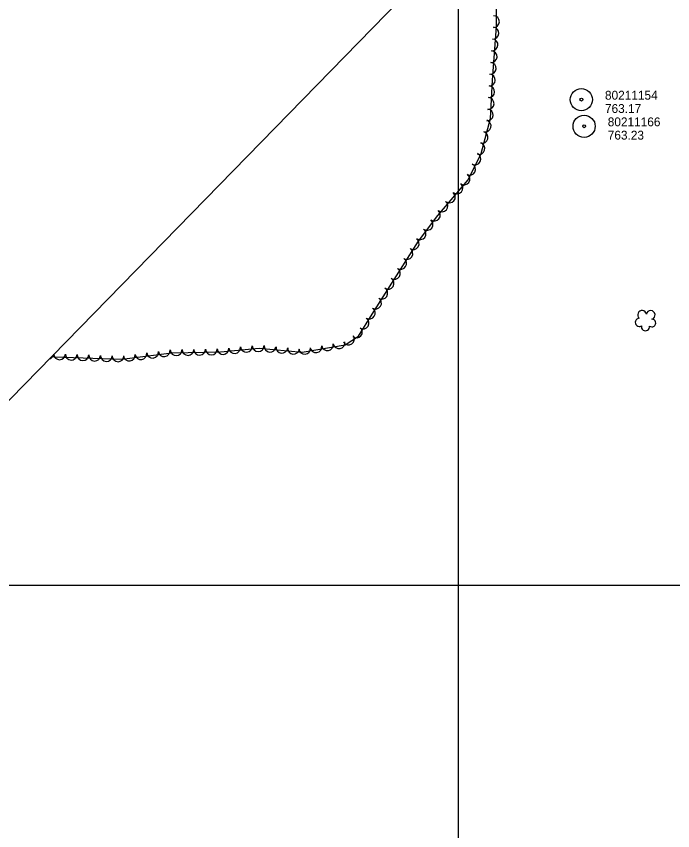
# Model space of a CAD drawing. Extents: x 591954 to 597000, y 198576 to 213500.
# Drawn here: x 593200 to 593645, y 205834 to 206385 of the extents above; entities that cross this region are included whole.
import ezdxf

# ---------------------------------------------------------------- set-up
doc = ezdxf.new("R2010")
doc.units = 0
for name, color, linetype in [('Level 10', 7, 'Continuous'), ('Level 18', 7, 'Continuous'), ('Level 4', 7, 'Continuous'), ('Level 6', 7, 'Continuous')]:
    doc.layers.add(name, color=color, linetype=linetype)

msp = doc.modelspace()

# ---------------------------------------------------------------- linework, layer by layer
at = {"layer": 'Level 10'}
for p, q in [((593500, 205500), (593500, 207000)), ((593500, 205500), (593500, 207000)), ((593500, 204500), (593500, 206500)), ((592000, 206000), (594000, 206000)), ((592500, 206000), (594000, 206000)), ((593000, 206000), (595500, 206000)), ((593500, 206000), (595500, 206000)), ((593500, 204500), (593500, 206000))]:
    msp.add_line(p, q, dxfattribs=at)
at = {"layer": 'Level 18'}
msp.add_lwpolyline([(593224.27, 206154.82), (593226.09, 206154.7), (593271.97, 206153.01), (593305.78, 206157.31), (593338.87, 206157.95), (593364.91, 206160.45), (593394.13, 206157.72), (593423.16, 206162.65), (593432.29, 206168.61), (593441.64, 206183.56), (593472.83, 206232.93), (593485.99, 206250.28), (593506.5, 206274.56), (593515.27, 206292.31), (593521.67, 206316.11), (593523.01, 206342.07), (593525.86, 206378.29), (593525.72, 206418.97), (593532.97, 206465.61), (593530.87, 206468.59)], dxfattribs=at)
for centre, radius, start, end in [((593523.75, 206381.59), 3.97, 269.813, 89.7976), ((593523.42, 206373.81), 3.97, 265.4895, 85.4742), ((593522.8, 206365.89), 3.97, 265.4973, 85.4819), ((593522.17, 206357.97), 3.97, 265.4895, 85.4742), ((593521.55, 206350.05), 3.97, 265.4967, 85.4814), ((593520.98, 206342.09), 3.97, 266.2991, 86.2838), ((593520.51, 206334.13), 3.97, 267.0722, 87.0568), ((593520.11, 206326.19), 3.97, 267.0722, 87.0568), ((593519.52, 206318.39), 3.96, 264.1336, 84.1182), ((593518.13, 206310.95), 3.97, 254.9536, 74.9383), ((593516.07, 206303.27), 3.97, 254.9536, 74.9383), ((593513.92, 206295.69), 3.96, 253.3555, 73.3402), ((593511.15, 206288.66), 3.97, 243.7102, 63.6949), ((593507.63, 206281.53), 3.97, 243.707, 63.6917), ((593503.76, 206275.03), 3.95, 234.6607, 54.6453), ((593499.01, 206268.92), 3.97, 229.8107, 49.7954), ((593493.88, 206262.85), 3.97, 229.8153, 49.8), ((593488.75, 206256.78), 3.97, 229.8107, 49.7954), ((593483.68, 206250.57), 3.97, 231.7804, 51.765), ((593478.8, 206244.25), 3.97, 232.8465, 52.8312), ((593474, 206237.92), 3.97, 232.8479, 52.8326), ((593469.36, 206231.27), 3.97, 237.2837, 57.2684), ((593465.08, 206224.56), 3.97, 237.7256, 57.7103), ((593460.84, 206217.84), 3.97, 237.7234, 57.708), ((593456.59, 206211.12), 3.97, 237.7195, 57.7042), ((593452.35, 206204.4), 3.97, 237.7234, 57.708), ((593448.1, 206197.69), 3.97, 237.7195, 57.7042), ((593443.86, 206190.97), 3.97, 237.7195, 57.7042), ((593439.62, 206184.24), 3.97, 237.8854, 57.87), ((593624.38, 206183.05), 2.97, 8.9237, 230.1575), ((593630.23, 206182.99), 2.97, 286.5745, 169.5477), ((593435.4, 206177.5), 3.97, 238.0015, 57.9862), ((593622.56, 206177.99), 2.78, 91.8946, 299.6675), ((593631.04, 206177.53), 2.61, 231.2797, 89.2123), ((593430.98, 206171.39), 3.89, 229.4966, 49.4813), ((593626.67, 206175.03), 2.78, 168.5716, 9.5826), ((593425.54, 206166.68), 3.97, 213.1418, 33.1265), ((593356.22, 206161.71), 3.97, 185.5023, 5.487), ((593364.3, 206162.15), 3.96, 180.8839, 0.8686), ((593372.43, 206161.84), 3.97, 174.6579, 354.6426), ((593380.35, 206161.1), 3.97, 174.6572, 354.6419), ((593403.45, 206161.41), 3.97, 189.6418, 9.6265), ((593411.28, 206162.74), 3.97, 189.649, 9.6336), ((593419.08, 206164.1), 3.96, 190.3028, 10.2875), ((593221.86, 206157.07), 3.97, 281.6047, 349.7176), ((593229.73, 206156.65), 3.97, 184.2163, 357.8), ((593237.67, 206156.35), 3.97, 177.902, 357.8867), ((593245.61, 206156.06), 3.97, 177.9018, 357.8865), ((593253.55, 206155.77), 3.97, 177.902, 357.8867), ((593277, 206155.75), 3.97, 187.2588, 7.2435), ((593284.88, 206156.75), 3.97, 187.2579, 7.2425), ((593292.77, 206157.75), 3.97, 187.2588, 7.2435), ((593300.65, 206158.76), 3.97, 187.2579, 7.2425), ((593308.76, 206159.4), 3.97, 181.826, 1.8106), ((593316.73, 206159.6), 3.97, 181.1108, 1.0954), ((593324.67, 206159.75), 3.97, 181.1035, 1.0882), ((593332.62, 206159.91), 3.97, 181.1109, 1.0956), ((593340.44, 206160.27), 3.97, 184.2675, 4.2522), ((593348.31, 206160.94), 3.97, 185.503, 5.4877), ((593388.26, 206160.36), 3.97, 174.6579, 354.6426), ((593395.75, 206160.36), 3.95, 185.6641, 5.6488), ((593261.5, 206155.48), 3.97, 177.902, 357.8867), ((593269.38, 206155.29), 3.97, 179.4948, 359.4795)]:
    msp.add_arc(centre, radius, start, end, dxfattribs=at)
at = {"layer": 'Level 4'}
msp.add_lwpolyline([(592724.44, 205643.32), (593573.84, 206512.56)], dxfattribs=at)
at = {"layer": 'Level 6'}
for centre, radius in [((593583.25, 206328.78), 7.5), ((593583.25, 206328.78), 7.5), ((593583.25, 206328.78), 7.5), ((593583.25, 206328.78), 0.96), ((593583.25, 206328.78), 0.96), ((593583.25, 206328.78), 0.96), ((593585.14, 206310.74), 7.5), ((593585.14, 206310.74), 7.5), ((593585.14, 206310.74), 7.5), ((593585.14, 206310.74), 0.96), ((593585.14, 206310.74), 0.96), ((593585.14, 206310.74), 0.96)]:
    msp.add_circle(centre, radius, dxfattribs=at)

# ---------------------------------------------------------------- texts
for s, p in [('80211154', (593599.25, 206328.78)), ('80211154', (593599.25, 206328.78)), ('80211154', (593599.25, 206328.78)), ('763.17', (593599.25, 206319.78)), ('763.17', (593599.25, 206319.78)), ('763.17', (593599.25, 206319.78)), ('80211166', (593601.14, 206310.74)), ('80211166', (593601.14, 206310.74)), ('80211166', (593601.14, 206310.74)), ('763.23', (593601.14, 206301.74)), ('763.23', (593601.14, 206301.74)), ('763.23', (593601.14, 206301.74))]:
    msp.add_text(s, height=6, dxfattribs=at).set_placement(p)

doc.saveas('drawing.dxf')
